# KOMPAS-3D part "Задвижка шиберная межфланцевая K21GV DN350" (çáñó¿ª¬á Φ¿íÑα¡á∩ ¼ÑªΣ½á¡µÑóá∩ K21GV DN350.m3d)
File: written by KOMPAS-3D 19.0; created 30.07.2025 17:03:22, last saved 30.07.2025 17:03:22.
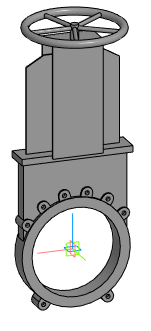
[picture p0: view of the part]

Document properties: Автор: Евгений; Полное имя файла: E:\Dendor Работа Сачек\3D для проектировщиков\2.3 Тип K21GV. Задвижка шиберная межфланцевая\stp_Задвижка шиберная K21GV DN50-400 с маховиком\Задвижка шиберная межфланцевая K21GV DN350.m3d

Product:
- Part/product: Задвижка шиберная межфланцевая K21GV DN350

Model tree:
1. Операция без истории:1  (labels: Задвижка шиберная межфланцевая K21GV DN350)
